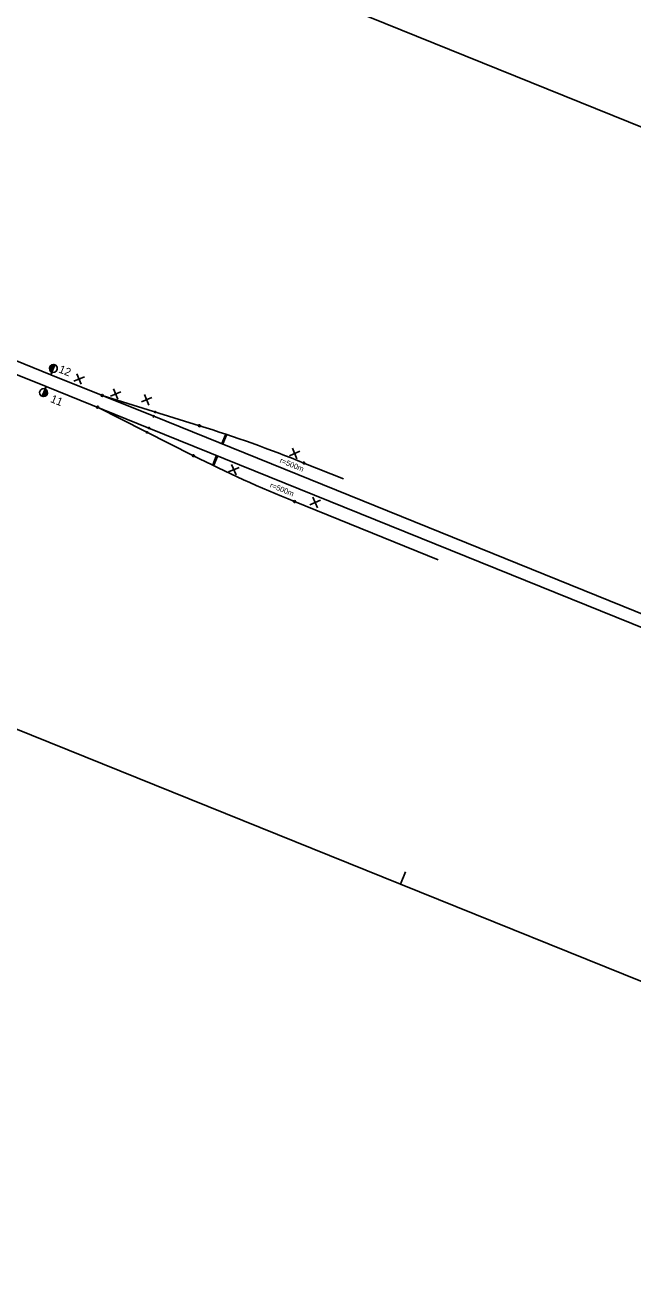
# Model space of a CAD drawing. Extents: x -467542 to -465211, y -1328177 to -1327037.
# Drawn here: x -466903.9 to -466676, y -1327774.3 to -1327304.7 of the extents above; entities that cross this region are included whole.
import ezdxf

# ---------------------------------------------------------------- set-up
doc = ezdxf.new("R2010")
doc.units = 0
for name, color, linetype in [('Level 1', 7, 'Continuous'), ('Level 10', 7, 'Continuous'), ('Level 11', 7, 'Continuous'), ('Level 61', 7, 'Continuous')]:
    doc.layers.add(name, color=color, linetype=linetype)

msp = doc.modelspace()

# ---------------------------------------------------------------- linework, layer by layer
at = {"layer": 'Level 1'}
for p, q in [((-466961.01, -1327408.74), (-466894.26, -1327435.74)), ((-466909.95, -1327434.51), (-466896.04, -1327440.14)), ((-466894.26, -1327435.74), (-466855.7, -1327451.33)), ((-466896.04, -1327440.14), (-466857.48, -1327455.73)), ((-466874.98, -1327443.53), (-466874.98, -1327443.53)), ((-466874.98, -1327443.53), (-466838.51, -1327454.86)), ((-466876.76, -1327447.94), (-466876.76, -1327447.94)), ((-466876.76, -1327447.94), (-466840.79, -1327466.09)), ((-466854.97, -1327449.23), (-466855.27, -1327450.18)), ((-466855.51, -1327450.87), (-466855.89, -1327451.79)), ((-466855.7, -1327451.33), (-466855.7, -1327451.33)), ((-466855.7, -1327451.33), (-466278.11, -1327684.94)), ((-466855.12, -1327449.7), (-466855.12, -1327449.7)), ((-466857.97, -1327456.86), (-466858.42, -1327457.75)), ((-466858.2, -1327457.31), (-466858.2, -1327457.31)), ((-466857.29, -1327455.27), (-466857.67, -1327456.2)), ((-466857.48, -1327455.73), (-466857.48, -1327455.73)), ((-466857.48, -1327455.73), (-466279.88, -1327689.35)), ((-466838.51, -1327454.86), (-466838.51, -1327454.86)), ((-466840.79, -1327466.09), (-466840.79, -1327466.09)), ((-466799.37, -1327468.83), (-466799.37, -1327468.83)), ((-466799.37, -1327468.83), (-466784.57, -1327474.82)), ((-466802.92, -1327483.27), (-466802.92, -1327483.27)), ((-466802.92, -1327483.27), (-466749.09, -1327505.16))]:
    msp.add_line(p, q, dxfattribs=at)
for points in [[(-466874.61, -1327443.68), (-466874.92, -1327443.93), (-466875.29, -1327443.78), (-466875.35, -1327443.38), (-466875.03, -1327443.14), (-466874.66, -1327443.29), (-466874.61, -1327443.68)], [(-466876.39, -1327448.08), (-466876.7, -1327448.33), (-466877.07, -1327448.18), (-466877.13, -1327447.78), (-466876.81, -1327447.54), (-466876.44, -1327447.69), (-466876.39, -1327448.08)], [(-466838.39, -1327454.48), (-466838.12, -1327454.77), (-466838.24, -1327455.15), (-466838.63, -1327455.24), (-466838.9, -1327454.95), (-466838.78, -1327454.57), (-466838.39, -1327454.48)], [(-466840.61, -1327465.74), (-466840.39, -1327466.07), (-466840.57, -1327466.43), (-466840.97, -1327466.45), (-466841.19, -1327466.11), (-466841.01, -1327465.76), (-466840.61, -1327465.74)], [(-466799.52, -1327469.2), (-466799.77, -1327468.89), (-466799.62, -1327468.52), (-466799.22, -1327468.46), (-466798.98, -1327468.78), (-466799.13, -1327469.15), (-466799.52, -1327469.2)], [(-466803.07, -1327483.64), (-466803.32, -1327483.33), (-466803.17, -1327482.96), (-466802.77, -1327482.9), (-466802.53, -1327483.22), (-466802.68, -1327483.59), (-466803.07, -1327483.64)]]:
    msp.add_lwpolyline(points, dxfattribs=at)
for centre, start, end in [((-466986.85, -1327932.35), 67.9787, 72.7419), ((-466615.45, -1327019.75), 243.2125, 247.9787)]:
    msp.add_arc(centre, 500, start, end, dxfattribs=at)
at = {"layer": 'Level 10'}
for p, q in [((-466828.82, -1327458.22), (-466830.13, -1327461.46)), ((-466828.4, -1327458.39), (-466829.71, -1327461.63)), ((-466832.22, -1327466.27), (-466833.53, -1327469.51)), ((-466831.8, -1327466.44), (-466833.11, -1327469.68))]:
    msp.add_line(p, q, dxfattribs=at)
at = {"layer": 'Level 11'}
for p, q in [((-466894.26, -1327435.74), (-466892.78, -1327432.07)), ((-466882.83, -1327439.33), (-466884.5, -1327435.4)), ((-466894.26, -1327435.74), (-466894.26, -1327435.74)), ((-466881.7, -1327436.53), (-466885.63, -1327438.2)), ((-466896.04, -1327440.14), (-466897.52, -1327443.8)), ((-466896.04, -1327440.14), (-466896.04, -1327440.14)), ((-466867.96, -1327442.15), (-466871.9, -1327443.82)), ((-466869.09, -1327444.96), (-466870.76, -1327441.02)), ((-466856.35, -1327444.28), (-466860.29, -1327445.96)), ((-466857.49, -1327447.09), (-466859.16, -1327443.15)), ((-466801.97, -1327467.26), (-466803.64, -1327463.32)), ((-466800.84, -1327464.45), (-466804.77, -1327466.12)), ((-466823.66, -1327470.46), (-466827.6, -1327472.13)), ((-466824.8, -1327473.27), (-466826.47, -1327469.33)), ((-466794.33, -1327485.61), (-466796, -1327481.67)), ((-466793.19, -1327482.8), (-466797.13, -1327484.48))]:
    msp.add_line(p, q, dxfattribs=at)
for points in [[(-466893.15, -1327431.92), (-466892.41, -1327432.22), (-466891.93, -1327432.85), (-466891.83, -1327433.6), (-466892.12, -1327434.32), (-466892.74, -1327434.8), (-466893.49, -1327434.91), (-466894.24, -1327434.61), (-466894.7, -1327434), (-466894.82, -1327433.25), (-466894.52, -1327432.5), (-466893.91, -1327432.04), (-466893.15, -1327431.92), (-466893.48, -1327432.06), (-466893.01, -1327432.25), (-466893.12, -1327432.53), (-466893.91, -1327432.21), (-466894.21, -1327432.41), (-466893.24, -1327432.8), (-466893.35, -1327433.08), (-466894.42, -1327432.65), (-466894.53, -1327432.93), (-466893.46, -1327433.36), (-466893.57, -1327433.64), (-466894.64, -1327433.21), (-466894.61, -1327433.54), (-466893.69, -1327433.92), (-466893.8, -1327434.2), (-466894.59, -1327433.88), (-466894.38, -1327434.29), (-466893.91, -1327434.47)], [(-466897.15, -1327443.95), (-466897.89, -1327443.65), (-466898.37, -1327443.02), (-466898.47, -1327442.28), (-466898.17, -1327441.54), (-466897.56, -1327441.07), (-466896.8, -1327440.96), (-466896.06, -1327441.26), (-466895.6, -1327441.87), (-466895.49, -1327442.64), (-466895.78, -1327443.36), (-466896.39, -1327443.84), (-466897.15, -1327443.95), (-466896.82, -1327443.81), (-466897.29, -1327443.62), (-466897.17, -1327443.35), (-466896.39, -1327443.66), (-466896.14, -1327443.44), (-466897.06, -1327443.07), (-466896.95, -1327442.79), (-466895.88, -1327443.22), (-466895.77, -1327442.94), (-466896.84, -1327442.51), (-466896.73, -1327442.23), (-466895.66, -1327442.66), (-466895.68, -1327442.33), (-466896.61, -1327441.96), (-466896.5, -1327441.68), (-466895.76, -1327441.98), (-466895.97, -1327441.57), (-466896.39, -1327441.4)]]:
    msp.add_lwpolyline(points, dxfattribs=at)
at = {"layer": 'Level 61'}
for p, q in [((-467430.68, -1327036.68), (-466651.85, -1327351.35)), ((-466763.11, -1327626.73), (-467541.94, -1327312.06)), ((-466763.11, -1327626.73), (-466761.23, -1327622.09)), ((-465400.15, -1328177.4), (-466763.11, -1327626.73))]:
    msp.add_line(p, q, dxfattribs=at)

# ---------------------------------------------------------------- texts
at = {"layer": 'Level 10'}
for p in [(-466808.65, -1327468.63), (-466812.34, -1327477.86)]:
    msp.add_text('r=500m', height=2, rotation=338, dxfattribs=at).set_placement(p)
at = {"layer": 'Level 11'}
for s, p in [('12', (-466891.58, -1327434.79)), ('11', (-466894.66, -1327445.9))]:
    msp.add_text(s, height=3, rotation=338, dxfattribs=at).set_placement(p)

doc.saveas('drawing.dxf')
